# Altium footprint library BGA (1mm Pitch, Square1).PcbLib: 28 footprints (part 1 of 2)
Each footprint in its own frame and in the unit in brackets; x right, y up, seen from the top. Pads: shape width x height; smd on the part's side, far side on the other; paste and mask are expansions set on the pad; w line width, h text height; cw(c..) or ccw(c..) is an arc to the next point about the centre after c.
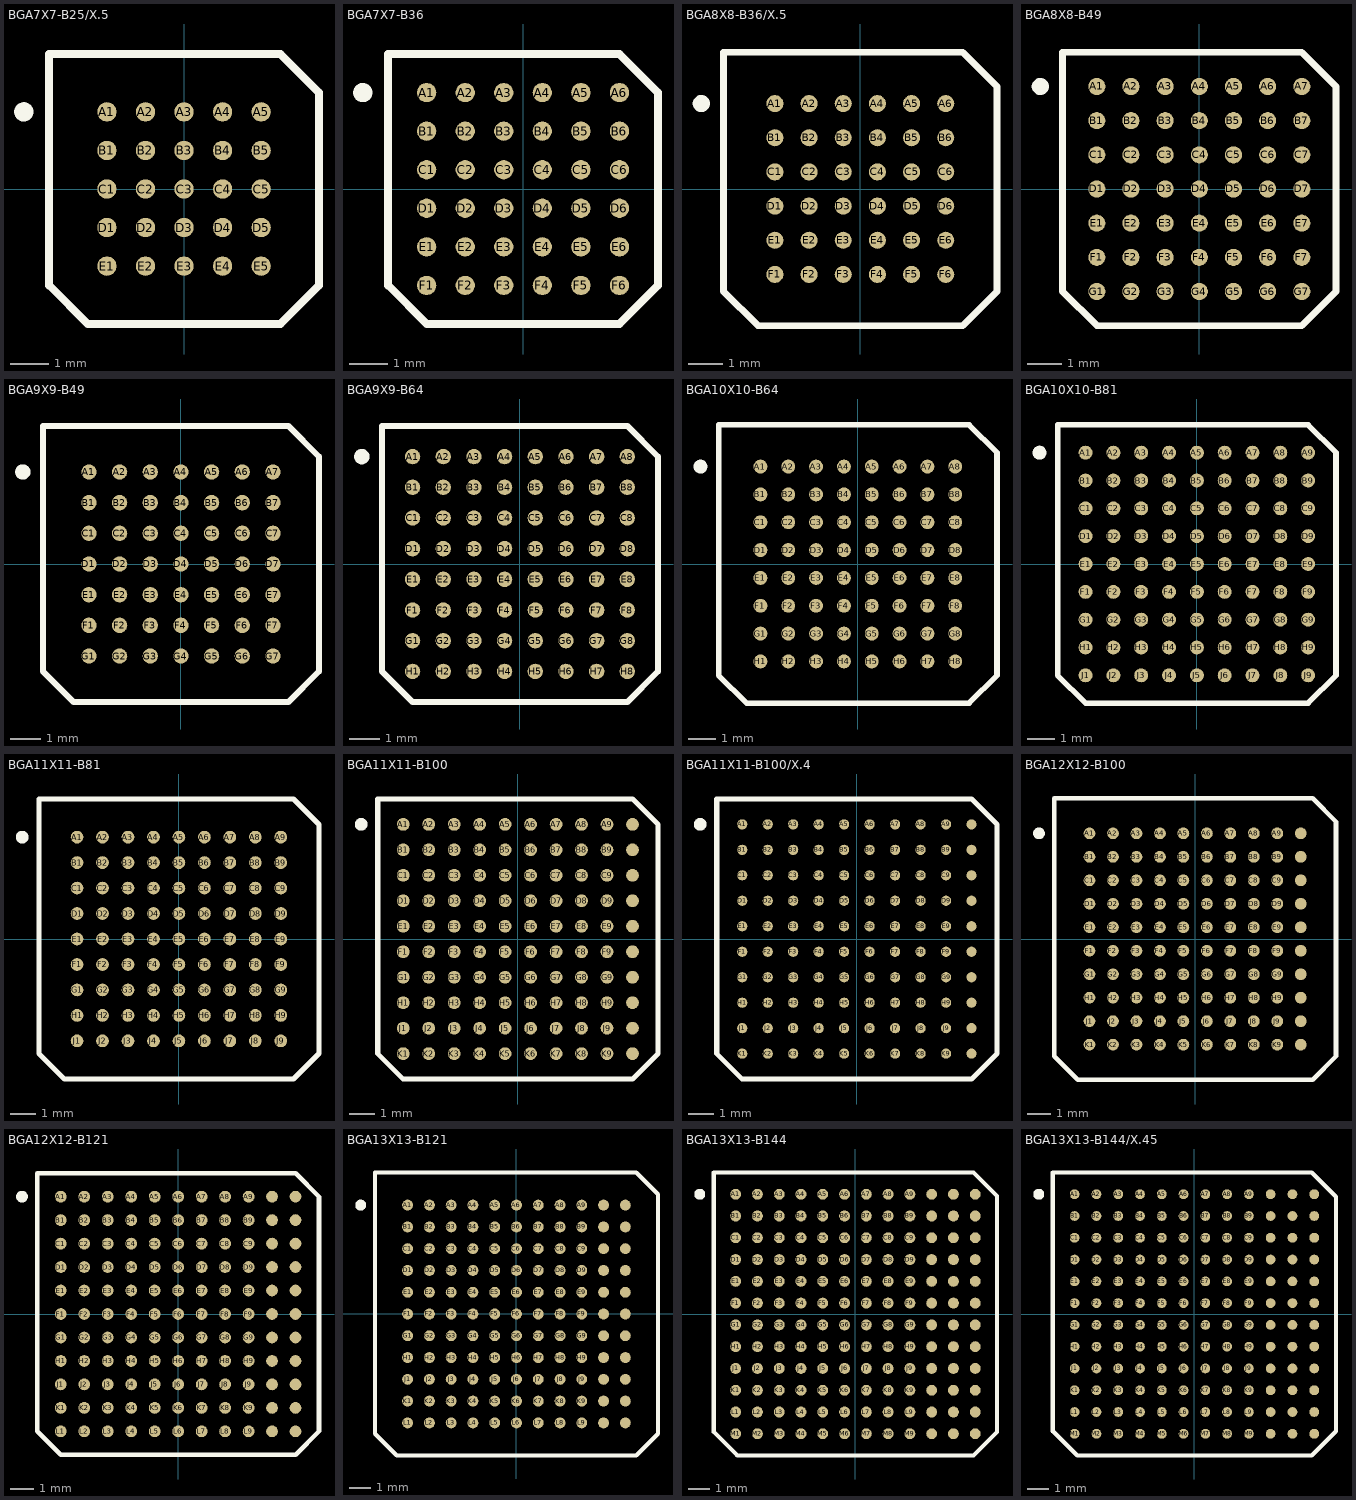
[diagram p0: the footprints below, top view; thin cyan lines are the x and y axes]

## BGA7X7-B25/X.5 [mm]
pads (25):
  round 0.5 smd: A1(-2,2) A2(-1,2) A3(0,2) A4(1,2) A5(2,2) B1(-2,1) B2(-1,1) B3(0,1) B4(1,1) B5(2,1) C1(-2,0) C2(-1,0) C3(0,0) C4(1,0) C5(2,0) D1(-2,-1) D2(-1,-1) D3(0,-1) D4(1,-1) D5(2,-1) E1(-2,-2) E2(-1,-2) E3(0,-2) E4(1,-2) E5(2,-2)
Top Overlay:
  circle w0.25: c-4.155,2 r0.125
  lines w0.2: -3.5,-2.5 -3.5,3.5 2.5,3.5 3.5,2.5 3.5,-2.5 2.5,-3.5 -2.5,-3.5 -3.5,-2.5

## BGA7X7-B36 [mm]
pads (36):
  round 0.5 smd: A1(-2.5,2.5) A2(-1.5,2.5) A3(-0.5,2.5) A4(0.5,2.5) A5(1.5,2.5) A6(2.5,2.5) B1(-2.5,1.5) B2(-1.5,1.5) B3(-0.5,1.5) B4(0.5,1.5) B5(1.5,1.5) B6(2.5,1.5) C1(-2.5,0.5) C2(-1.5,0.5) C3(-0.5,0.5) C4(0.5,0.5) C5(1.5,0.5) C6(2.5,0.5) D1(-2.5,-0.5) D2(-1.5,-0.5) D3(-0.5,-0.5) D4(0.5,-0.5) D5(1.5,-0.5) D6(2.5,-0.5) E1(-2.5,-1.5) E2(-1.5,-1.5) E3(-0.5,-1.5) E4(0.5,-1.5) E5(1.5,-1.5) E6(2.5,-1.5) F1(-2.5,-2.5) F2(-1.5,-2.5) F3(-0.5,-2.5) F4(0.5,-2.5) F5(1.5,-2.5) F6(2.5,-2.5)
Top Overlay:
  circle w0.25: c-4.155,2.5 r0.125
  lines w0.2: -3.5,-2.5 -2.5,-3.5 2.5,-3.5 3.5,-2.5 3.5,2.5 2.5,3.5 -3.5,3.5 -3.5,-2.5

## BGA8X8-B36/X.5 [mm]
pads (36):
  round 0.5 smd: A1(-2.5,2.5) A2(-1.5,2.5) A3(-0.5,2.5) A4(0.5,2.5) A5(1.5,2.5) A6(2.5,2.5) B1(-2.5,1.5) B2(-1.5,1.5) B3(-0.5,1.5) B4(0.5,1.5) B5(1.5,1.5) B6(2.5,1.5) C1(-2.5,0.5) C2(-1.5,0.5) C3(-0.5,0.5) C4(0.5,0.5) C5(1.5,0.5) C6(2.5,0.5) D1(-2.5,-0.5) D2(-1.5,-0.5) D3(-0.5,-0.5) D4(0.5,-0.5) D5(1.5,-0.5) D6(2.5,-0.5) E1(-2.5,-1.5) E2(-1.5,-1.5) E3(-0.5,-1.5) E4(0.5,-1.5) E5(1.5,-1.5) E6(2.5,-1.5) F1(-2.5,-2.5) F2(-1.5,-2.5) F3(-0.5,-2.5) F4(0.5,-2.5) F5(1.5,-2.5) F6(2.5,-2.5)
Top Overlay:
  circle w0.25: c-4.655,2.5 r0.125
  lines w0.2: -4,-3 -3,-4 3,-4 4,-3 4,3 3,4 -4,4 -4,-3

## BGA8X8-B49 [mm]
pads (49):
  round 0.5 smd: A1(-3,3) A2(-2,3) A3(-1,3) A4(0,3) A5(1,3) A6(2,3) A7(3,3) B1(-3,2) B2(-2,2) B3(-1,2) B4(0,2) B5(1,2) B6(2,2) B7(3,2) C1(-3,1) C2(-2,1) C3(-1,1) C4(0,1) C5(1,1) C6(2,1) C7(3,1) D1(-3,0) D2(-2,0) D3(-1,0) D4(0,0) D5(1,0) D6(2,0) D7(3,0) E1(-3,-1) E2(-2,-1) E3(-1,-1) E4(0,-1) E5(1,-1) E6(2,-1) E7(3,-1) F1(-3,-2) F2(-2,-2) F3(-1,-2) F4(0,-2) F5(1,-2) F6(2,-2) F7(3,-2) G1(-3,-3) G2(-2,-3) G3(-1,-3) G4(0,-3) G5(1,-3) G6(2,-3) G7(3,-3)
Top Overlay:
  circle w0.25: c-4.655,3 r0.125
  lines w0.2: -4,-3 -3,-4 3,-4 4,-3 4,3 3,4 -4,4 -4,-3

## BGA9X9-B49 [mm]
pads (49):
  round 0.5 smd: A1(-3,3) A2(-2,3) A3(-1,3) A4(0,3) A5(1,3) A6(2,3) A7(3,3) B1(-3,2) B2(-2,2) B3(-1,2) B4(0,2) B5(1,2) B6(2,2) B7(3,2) C1(-3,1) C2(-2,1) C3(-1,1) C4(0,1) C5(1,1) C6(2,1) C7(3,1) D1(-3,0) D2(-2,0) D3(-1,0) D4(0,0) D5(1,0) D6(2,0) D7(3,0) E1(-3,-1) E2(-2,-1) E3(-1,-1) E4(0,-1) E5(1,-1) E6(2,-1) E7(3,-1) F1(-3,-2) F2(-2,-2) F3(-1,-2) F4(0,-2) F5(1,-2) F6(2,-2) F7(3,-2) G1(-3,-3) G2(-2,-3) G3(-1,-3) G4(0,-3) G5(1,-3) G6(2,-3) G7(3,-3)
Top Overlay:
  circle w0.25: c-5.155,3 r0.125
  lines w0.2: -4.5,-3.5 -3.5,-4.5 3.5,-4.5 4.5,-3.5 4.5,3.5 3.5,4.5 -4.5,4.5 -4.5,-3.5

## BGA9X9-B64 [mm]
pads (64):
  round 0.5 smd: A1(-3.5,3.5) A2(-2.5,3.5) A3(-1.5,3.5) A4(-0.5,3.5) A5(0.5,3.5) A6(1.5,3.5) A7(2.5,3.5) A8(3.5,3.5) B1(-3.5,2.5) B2(-2.5,2.5) B3(-1.5,2.5) B4(-0.5,2.5) B5(0.5,2.5) B6(1.5,2.5) B7(2.5,2.5) B8(3.5,2.5) C1(-3.5,1.5) C2(-2.5,1.5) C3(-1.5,1.5) C4(-0.5,1.5) C5(0.5,1.5) C6(1.5,1.5) C7(2.5,1.5) C8(3.5,1.5) D1(-3.5,0.5) D2(-2.5,0.5) D3(-1.5,0.5) D4(-0.5,0.5) D5(0.5,0.5) D6(1.5,0.5) D7(2.5,0.5) D8(3.5,0.5) E1(-3.5,-0.5) E2(-2.5,-0.5) E3(-1.5,-0.5) E4(-0.5,-0.5) E5(0.5,-0.5) E6(1.5,-0.5) E7(2.5,-0.5) E8(3.5,-0.5) F1(-3.5,-1.5) F2(-2.5,-1.5) F3(-1.5,-1.5) F4(-0.5,-1.5) F5(0.5,-1.5) F6(1.5,-1.5) F7(2.5,-1.5) F8(3.5,-1.5) G1(-3.5,-2.5) G2(-2.5,-2.5) G3(-1.5,-2.5) G4(-0.5,-2.5) G5(0.5,-2.5) G6(1.5,-2.5) G7(2.5,-2.5) G8(3.5,-2.5) H1(-3.5,-3.5) H2(-2.5,-3.5) H3(-1.5,-3.5) H4(-0.5,-3.5) H5(0.5,-3.5) H6(1.5,-3.5) H7(2.5,-3.5) H8(3.5,-3.5)
Top Overlay:
  circle w0.25: c-5.155,3.5 r0.125
  lines w0.2: -4.5,-3.5 -4.5,4.5 3.5,4.5 4.5,3.5 4.5,-3.5 3.5,-4.5 -3.5,-4.5 -4.5,-3.5

## BGA10X10-B64 [mm]
pads (64):
  round 0.5 smd: A1(-3.5,3.5) A2(-2.5,3.5) A3(-1.5,3.5) A4(-0.5,3.5) A5(0.5,3.5) A6(1.5,3.5) A7(2.5,3.5) A8(3.5,3.5) B1(-3.5,2.5) B2(-2.5,2.5) B3(-1.5,2.5) B4(-0.5,2.5) B5(0.5,2.5) B6(1.5,2.5) B7(2.5,2.5) B8(3.5,2.5) C1(-3.5,1.5) C2(-2.5,1.5) C3(-1.5,1.5) C4(-0.5,1.5) C5(0.5,1.5) C6(1.5,1.5) C7(2.5,1.5) C8(3.5,1.5) D1(-3.5,0.5) D2(-2.5,0.5) D3(-1.5,0.5) D4(-0.5,0.5) D5(0.5,0.5) D6(1.5,0.5) D7(2.5,0.5) D8(3.5,0.5) E1(-3.5,-0.5) E2(-2.5,-0.5) E3(-1.5,-0.5) E4(-0.5,-0.5) E5(0.5,-0.5) E6(1.5,-0.5) E7(2.5,-0.5) E8(3.5,-0.5) F1(-3.5,-1.5) F2(-2.5,-1.5) F3(-1.5,-1.5) F4(-0.5,-1.5) F5(0.5,-1.5) F6(1.5,-1.5) F7(2.5,-1.5) F8(3.5,-1.5) G1(-3.5,-2.5) G2(-2.5,-2.5) G3(-1.5,-2.5) G4(-0.5,-2.5) G5(0.5,-2.5) G6(1.5,-2.5) G7(2.5,-2.5) G8(3.5,-2.5) H1(-3.5,-3.5) H2(-2.5,-3.5) H3(-1.5,-3.5) H4(-0.5,-3.5) H5(0.5,-3.5) H6(1.5,-3.5) H7(2.5,-3.5) H8(3.5,-3.5)
Top Overlay:
  circle w0.25: c-5.655,3.5 r0.125
  lines w0.2: -5,-4 -4,-5 4,-5 5,-4 5,4 4,5 -5,5 -5,-4

## BGA10X10-B81 [mm]
pads (81):
  round 0.5 smd: A1(-4,4) A2(-3,4) A3(-2,4) A4(-1,4) A5(0,4) A6(1,4) A7(2,4) A8(3,4) A9(4,4) B1(-4,3) B2(-3,3) B3(-2,3) B4(-1,3) B5(0,3) B6(1,3) B7(2,3) B8(3,3) B9(4,3) C1(-4,2) C2(-3,2) C3(-2,2) C4(-1,2) C5(0,2) C6(1,2) C7(2,2) C8(3,2) C9(4,2) D1(-4,1) D2(-3,1) D3(-2,1) D4(-1,1) D5(0,1) D6(1,1) D7(2,1) D8(3,1) D9(4,1) E1(-4,0) E2(-3,0) E3(-2,0) E4(-1,0) E5(0,0) E6(1,0) E7(2,0) E8(3,0) E9(4,0) F1(-4,-1) F2(-3,-1) F3(-2,-1) F4(-1,-1) F5(0,-1) F6(1,-1) F7(2,-1) F8(3,-1) F9(4,-1) G1(-4,-2) G2(-3,-2) G3(-2,-2) G4(-1,-2) G5(0,-2) G6(1,-2) G7(2,-2) G8(3,-2) G9(4,-2) H1(-4,-3) H2(-3,-3) H3(-2,-3) H4(-1,-3) H5(0,-3) H6(1,-3) H7(2,-3) H8(3,-3) H9(4,-3) J1(-4,-4) J2(-3,-4) J3(-2,-4) J4(-1,-4) J5(0,-4) J6(1,-4) J7(2,-4) J8(3,-4) J9(4,-4)
Top Overlay:
  circle w0.25: c-5.655,4 r0.125
  lines w0.2: -5,-4 -4,-5 4,-5 5,-4 5,4 4,5 -5,5 -5,-4

## BGA11X11-B81 [mm]
pads (81):
  round 0.5 smd: A1(-4,4) A2(-3,4) A3(-2,4) A4(-1,4) A5(0,4) A6(1,4) A7(2,4) A8(3,4) A9(4,4) B1(-4,3) B2(-3,3) B3(-2,3) B4(-1,3) B5(0,3) B6(1,3) B7(2,3) B8(3,3) B9(4,3) C1(-4,2) C2(-3,2) C3(-2,2) C4(-1,2) C5(0,2) C6(1,2) C7(2,2) C8(3,2) C9(4,2) D1(-4,1) D2(-3,1) D3(-2,1) D4(-1,1) D5(0,1) D6(1,1) D7(2,1) D8(3,1) D9(4,1) E1(-4,0) E2(-3,0) E3(-2,0) E4(-1,0) E5(0,0) E6(1,0) E7(2,0) E8(3,0) E9(4,0) F1(-4,-1) F2(-3,-1) F3(-2,-1) F4(-1,-1) F5(0,-1) F6(1,-1) F7(2,-1) F8(3,-1) F9(4,-1) G1(-4,-2) G2(-3,-2) G3(-2,-2) G4(-1,-2) G5(0,-2) G6(1,-2) G7(2,-2) G8(3,-2) G9(4,-2) H1(-4,-3) H2(-3,-3) H3(-2,-3) H4(-1,-3) H5(0,-3) H6(1,-3) H7(2,-3) H8(3,-3) H9(4,-3) J1(-4,-4) J2(-3,-4) J3(-2,-4) J4(-1,-4) J5(0,-4) J6(1,-4) J7(2,-4) J8(3,-4) J9(4,-4)
Top Overlay:
  circle w0.25: c-6.155,4 r0.125
  lines w0.2: -5.5,-4.5 -5.5,5.5 4.5,5.5 5.5,4.5 5.5,-4.5 4.5,-5.5 -4.5,-5.5 -5.5,-4.5

## BGA11X11-B100 [mm]
pads (100):
  round 0.5 smd: A1(-4.5,4.5) A2(-3.5,4.5) A3(-2.5,4.5) A4(-1.5,4.5) A5(-0.5,4.5) A6(0.5,4.5) A7(1.5,4.5) A8(2.5,4.5) A9(3.5,4.5) A10(4.5,4.5) B1(-4.5,3.5) B2(-3.5,3.5) B3(-2.5,3.5) B4(-1.5,3.5) B5(-0.5,3.5) B6(0.5,3.5) B7(1.5,3.5) B8(2.5,3.5) B9(3.5,3.5) B10(4.5,3.5) C1(-4.5,2.5) C2(-3.5,2.5) C3(-2.5,2.5) C4(-1.5,2.5) C5(-0.5,2.5) C6(0.5,2.5) C7(1.5,2.5) C8(2.5,2.5) C9(3.5,2.5) C10(4.5,2.5) D1(-4.5,1.5) D2(-3.5,1.5) D3(-2.5,1.5) D4(-1.5,1.5) D5(-0.5,1.5) D6(0.5,1.5) D7(1.5,1.5) D8(2.5,1.5) D9(3.5,1.5) D10(4.5,1.5) E1(-4.5,0.5) E2(-3.5,0.5) E3(-2.5,0.5) E4(-1.5,0.5) E5(-0.5,0.5) E6(0.5,0.5) E7(1.5,0.5) E8(2.5,0.5) E9(3.5,0.5) E10(4.5,0.5) F1(-4.5,-0.5) F2(-3.5,-0.5) F3(-2.5,-0.5) F4(-1.5,-0.5) F5(-0.5,-0.5) F6(0.5,-0.5) F7(1.5,-0.5) F8(2.5,-0.5) F9(3.5,-0.5) F10(4.5,-0.5) G1(-4.5,-1.5) G2(-3.5,-1.5) G3(-2.5,-1.5) G4(-1.5,-1.5) G5(-0.5,-1.5) G6(0.5,-1.5) G7(1.5,-1.5) G8(2.5,-1.5) G9(3.5,-1.5) G10(4.5,-1.5) H1(-4.5,-2.5) H2(-3.5,-2.5) H3(-2.5,-2.5) H4(-1.5,-2.5) H5(-0.5,-2.5) H6(0.5,-2.5) H7(1.5,-2.5) H8(2.5,-2.5) H9(3.5,-2.5) H10(4.5,-2.5) J1(-4.5,-3.5) J2(-3.5,-3.5) J3(-2.5,-3.5) J4(-1.5,-3.5) J5(-0.5,-3.5) J6(0.5,-3.5) J7(1.5,-3.5) J8(2.5,-3.5) J9(3.5,-3.5) J10(4.5,-3.5) K1(-4.5,-4.5) K2(-3.5,-4.5) K3(-2.5,-4.5) K4(-1.5,-4.5) K5(-0.5,-4.5) K6(0.5,-4.5) K7(1.5,-4.5) K8(2.5,-4.5) K9(3.5,-4.5) K10(4.5,-4.5)
Top Overlay:
  circle w0.25: c-6.15,4.5 r0.125
  lines w0.2: -5.5,-4.5 -5.5,5.5 4.5,5.5 5.5,4.5 5.5,-4.5 4.5,-5.5 -4.5,-5.5 -5.5,-4.5

## BGA11X11-B100/X.4 [mm]
pads (100):
  round 0.4 smd: A1(-4.5,4.5) A2(-3.5,4.5) A3(-2.5,4.5) A4(-1.5,4.5) A5(-0.5,4.5) A6(0.5,4.5) A7(1.5,4.5) A8(2.5,4.5) A9(3.5,4.5) A10(4.5,4.5) B1(-4.5,3.5) B2(-3.5,3.5) B3(-2.5,3.5) B4(-1.5,3.5) B5(-0.5,3.5) B6(0.5,3.5) B7(1.5,3.5) B8(2.5,3.5) B9(3.5,3.5) B10(4.5,3.5) C1(-4.5,2.5) C2(-3.5,2.5) C3(-2.5,2.5) C4(-1.5,2.5) C5(-0.5,2.5) C6(0.5,2.5) C7(1.5,2.5) C8(2.5,2.5) C9(3.5,2.5) C10(4.5,2.5) D1(-4.5,1.5) D2(-3.5,1.5) D3(-2.5,1.5) D4(-1.5,1.5) D5(-0.5,1.5) D6(0.5,1.5) D7(1.5,1.5) D8(2.5,1.5) D9(3.5,1.5) D10(4.5,1.5) E1(-4.5,0.5) E2(-3.5,0.5) E3(-2.5,0.5) E4(-1.5,0.5) E5(-0.5,0.5) E6(0.5,0.5) E7(1.5,0.5) E8(2.5,0.5) E9(3.5,0.5) E10(4.5,0.5) F1(-4.5,-0.5) F2(-3.5,-0.5) F3(-2.5,-0.5) F4(-1.5,-0.5) F5(-0.5,-0.5) F6(0.5,-0.5) F7(1.5,-0.5) F8(2.5,-0.5) F9(3.5,-0.5) F10(4.5,-0.5) G1(-4.5,-1.5) G2(-3.5,-1.5) G3(-2.5,-1.5) G4(-1.5,-1.5) G5(-0.5,-1.5) G6(0.5,-1.5) G7(1.5,-1.5) G8(2.5,-1.5) G9(3.5,-1.5) G10(4.5,-1.5) H1(-4.5,-2.5) H2(-3.5,-2.5) H3(-2.5,-2.5) H4(-1.5,-2.5) H5(-0.5,-2.5) H6(0.5,-2.5) H7(1.5,-2.5) H8(2.5,-2.5) H9(3.5,-2.5) H10(4.5,-2.5) J1(-4.5,-3.5) J2(-3.5,-3.5) J3(-2.5,-3.5) J4(-1.5,-3.5) J5(-0.5,-3.5) J6(0.5,-3.5) J7(1.5,-3.5) J8(2.5,-3.5) J9(3.5,-3.5) J10(4.5,-3.5) K1(-4.5,-4.5) K2(-3.5,-4.5) K3(-2.5,-4.5) K4(-1.5,-4.5) K5(-0.5,-4.5) K6(0.5,-4.5) K7(1.5,-4.5) K8(2.5,-4.5) K9(3.5,-4.5) K10(4.5,-4.5)
Top Overlay:
  circle w0.25: c-6.15,4.5 r0.125
  lines w0.2: -5.5,-4.5 -5.5,5.5 4.5,5.5 5.5,4.5 5.5,-4.5 4.5,-5.5 -4.5,-5.5 -5.5,-4.5

## BGA12X12-B100 [mm]
pads (100):
  round 0.5 smd: A1(-4.5,4.5) A2(-3.5,4.5) A3(-2.5,4.5) A4(-1.5,4.5) A5(-0.5,4.5) A6(0.5,4.5) A7(1.5,4.5) A8(2.5,4.5) A9(3.5,4.5) A10(4.5,4.5) B1(-4.5,3.5) B2(-3.5,3.5) B3(-2.5,3.5) B4(-1.5,3.5) B5(-0.5,3.5) B6(0.5,3.5) B7(1.5,3.5) B8(2.5,3.5) B9(3.5,3.5) B10(4.5,3.5) C1(-4.5,2.5) C2(-3.5,2.5) C3(-2.5,2.5) C4(-1.5,2.5) C5(-0.5,2.5) C6(0.5,2.5) C7(1.5,2.5) C8(2.5,2.5) C9(3.5,2.5) C10(4.5,2.5) D1(-4.5,1.5) D2(-3.5,1.5) D3(-2.5,1.5) D4(-1.5,1.5) D5(-0.5,1.5) D6(0.5,1.5) D7(1.5,1.5) D8(2.5,1.5) D9(3.5,1.5) D10(4.5,1.5) E1(-4.5,0.5) E2(-3.5,0.5) E3(-2.5,0.5) E4(-1.5,0.5) E5(-0.5,0.5) E6(0.5,0.5) E7(1.5,0.5) E8(2.5,0.5) E9(3.5,0.5) E10(4.5,0.5) F1(-4.5,-0.5) F2(-3.5,-0.5) F3(-2.5,-0.5) F4(-1.5,-0.5) F5(-0.5,-0.5) F6(0.5,-0.5) F7(1.5,-0.5) F8(2.5,-0.5) F9(3.5,-0.5) F10(4.5,-0.5) G1(-4.5,-1.5) G2(-3.5,-1.5) G3(-2.5,-1.5) G4(-1.5,-1.5) G5(-0.5,-1.5) G6(0.5,-1.5) G7(1.5,-1.5) G8(2.5,-1.5) G9(3.5,-1.5) G10(4.5,-1.5) H1(-4.5,-2.5) H2(-3.5,-2.5) H3(-2.5,-2.5) H4(-1.5,-2.5) H5(-0.5,-2.5) H6(0.5,-2.5) H7(1.5,-2.5) H8(2.5,-2.5) H9(3.5,-2.5) H10(4.5,-2.5) J1(-4.5,-3.5) J2(-3.5,-3.5) J3(-2.5,-3.5) J4(-1.5,-3.5) J5(-0.5,-3.5) J6(0.5,-3.5) J7(1.5,-3.5) J8(2.5,-3.5) J9(3.5,-3.5) J10(4.5,-3.5) K1(-4.5,-4.5) K2(-3.5,-4.5) K3(-2.5,-4.5) K4(-1.5,-4.5) K5(-0.5,-4.5) K6(0.5,-4.5) K7(1.5,-4.5) K8(2.5,-4.5) K9(3.5,-4.5) K10(4.5,-4.5)
Top Overlay:
  circle w0.25: c-6.655,4.5 r0.125
  lines w0.2: -6,-5 -5,-6 5,-6 6,-5 6,5 5,6 -6,6 -6,-5

## BGA12X12-B121 [mm]
pads (121):
  round 0.5 smd: A1(-5,5) A2(-4,5) A3(-3,5) A4(-2,5) A5(-1,5) A6(0,5) A7(1,5) A8(2,5) A9(3,5) A10(4,5) A11(5,5) B1(-5,4) B2(-4,4) B3(-3,4) B4(-2,4) B5(-1,4) B6(0,4) B7(1,4) B8(2,4) B9(3,4) B10(4,4) B11(5,4) C1(-5,3) C2(-4,3) C3(-3,3) C4(-2,3) C5(-1,3) C6(0,3) C7(1,3) C8(2,3) C9(3,3) C10(4,3) C11(5,3) D1(-5,2) D2(-4,2) D3(-3,2) D4(-2,2) D5(-1,2) D6(0,2) D7(1,2) D8(2,2) D9(3,2) D10(4,2) D11(5,2) E1(-5,1) E2(-4,1) E3(-3,1) E4(-2,1) E5(-1,1) E6(0,1) E7(1,1) E8(2,1) E9(3,1) E10(4,1) E11(5,1) F1(-5,0) F2(-4,0) F3(-3,0) F4(-2,0) F5(-1,0) F6(0,0) F7(1,0) F8(2,0) F9(3,0) F10(4,0) F11(5,0) G1(-5,-1) G2(-4,-1) G3(-3,-1) G4(-2,-1) G5(-1,-1) G6(0,-1) G7(1,-1) G8(2,-1) G9(3,-1) G10(4,-1) G11(5,-1) H1(-5,-2) H2(-4,-2) H3(-3,-2) H4(-2,-2) H5(-1,-2) H6(0,-2) H7(1,-2) H8(2,-2) H9(3,-2) H10(4,-2) H11(5,-2) J1(-5,-3) J2(-4,-3) J3(-3,-3) J4(-2,-3) J5(-1,-3) J6(0,-3) J7(1,-3) J8(2,-3) J9(3,-3) J10(4,-3) J11(5,-3) K1(-5,-4) K2(-4,-4) K3(-3,-4) K4(-2,-4) K5(-1,-4) K6(0,-4) K7(1,-4) K8(2,-4) K9(3,-4) K10(4,-4) K11(5,-4) L1(-5,-5) L2(-4,-5) L3(-3,-5) L4(-2,-5) L5(-1,-5) L6(0,-5) L7(1,-5) L8(2,-5) L9(3,-5) L10(4,-5) L11(5,-5)
Top Overlay:
  circle w0.25: c-6.655,5 r0.125
  lines w0.2: -6,-5 -5,-6 5,-6 6,-5 6,5 5,6 -6,6 -6,-5

## BGA13X13-B121 [mm]
pads (121):
  round 0.5 smd: A1(-5,5) A2(-4,5) A3(-3,5) A4(-2,5) A5(-1,5) A6(0,5) A7(1,5) A8(2,5) A9(3,5) A10(4,5) A11(5,5) B1(-5,4) B2(-4,4) B3(-3,4) B4(-2,4) B5(-1,4) B6(0,4) B7(1,4) B8(2,4) B9(3,4) B10(4,4) B11(5,4) C1(-5,3) C2(-4,3) C3(-3,3) C4(-2,3) C5(-1,3) C6(0,3) C7(1,3) C8(2,3) C9(3,3) C10(4,3) C11(5,3) D1(-5,2) D2(-4,2) D3(-3,2) D4(-2,2) D5(-1,2) D6(0,2) D7(1,2) D8(2,2) D9(3,2) D10(4,2) D11(5,2) E1(-5,1) E2(-4,1) E3(-3,1) E4(-2,1) E5(-1,1) E6(0,1) E7(1,1) E8(2,1) E9(3,1) E10(4,1) E11(5,1) F1(-5,0) F2(-4,0) F3(-3,0) F4(-2,0) F5(-1,0) F6(0,0) F7(1,0) F8(2,0) F9(3,0) F10(4,0) F11(5,0) G1(-5,-1) G2(-4,-1) G3(-3,-1) G4(-2,-1) G5(-1,-1) G6(0,-1) G7(1,-1) G8(2,-1) G9(3,-1) G10(4,-1) G11(5,-1) H1(-5,-2) H2(-4,-2) H3(-3,-2) H4(-2,-2) H5(-1,-2) H6(0,-2) H7(1,-2) H8(2,-2) H9(3,-2) H10(4,-2) H11(5,-2) J1(-5,-3) J2(-4,-3) J3(-3,-3) J4(-2,-3) J5(-1,-3) J6(0,-3) J7(1,-3) J8(2,-3) J9(3,-3) J10(4,-3) J11(5,-3) K1(-5,-4) K2(-4,-4) K3(-3,-4) K4(-2,-4) K5(-1,-4) K6(0,-4) K7(1,-4) K8(2,-4) K9(3,-4) K10(4,-4) K11(5,-4) L1(-5,-5) L2(-4,-5) L3(-3,-5) L4(-2,-5) L5(-1,-5) L6(0,-5) L7(1,-5) L8(2,-5) L9(3,-5) L10(4,-5) L11(5,-5)
Top Overlay:
  circle w0.25: c-7.155,5 r0.125
  lines w0.2: -6.5,-5.5 -5.5,-6.5 5.5,-6.5 6.5,-5.5 6.5,5.5 5.5,6.5 -6.5,6.5 -6.5,-5.5

## BGA13X13-B144 [mm]
pads (144):
  round 0.5 smd: A1(-5.5,5.5) A2(-4.5,5.5) A3(-3.5,5.5) A4(-2.5,5.5) A5(-1.5,5.5) A6(-0.5,5.5) A7(0.5,5.5) A8(1.5,5.5) A9(2.5,5.5) A10(3.5,5.5) A11(4.5,5.5) A12(5.5,5.5) B1(-5.5,4.5) B2(-4.5,4.5) B3(-3.5,4.5) B4(-2.5,4.5) B5(-1.5,4.5) B6(-0.5,4.5) B7(0.5,4.5) B8(1.5,4.5) B9(2.5,4.5) B10(3.5,4.5) B11(4.5,4.5) B12(5.5,4.5) C1(-5.5,3.5) C2(-4.5,3.5) C3(-3.5,3.5) C4(-2.5,3.5) C5(-1.5,3.5) C6(-0.5,3.5) C7(0.5,3.5) C8(1.5,3.5) C9(2.5,3.5) C10(3.5,3.5) C11(4.5,3.5) C12(5.5,3.5) D1(-5.5,2.5) D2(-4.5,2.5) D3(-3.5,2.5) D4(-2.5,2.5) D5(-1.5,2.5) D6(-0.5,2.5) D7(0.5,2.5) D8(1.5,2.5) D9(2.5,2.5) D10(3.5,2.5) D11(4.5,2.5) D12(5.5,2.5) E1(-5.5,1.5) E2(-4.5,1.5) E3(-3.5,1.5) E4(-2.5,1.5) E5(-1.5,1.5) E6(-0.5,1.5) E7(0.5,1.5) E8(1.5,1.5) E9(2.5,1.5) E10(3.5,1.5) E11(4.5,1.5) E12(5.5,1.5) F1(-5.5,0.5) F2(-4.5,0.5) F3(-3.5,0.5) F4(-2.5,0.5) F5(-1.5,0.5) F6(-0.5,0.5) F7(0.5,0.5) F8(1.5,0.5) F9(2.5,0.5) F10(3.5,0.5) F11(4.5,0.5) F12(5.5,0.5) G1(-5.5,-0.5) G2(-4.5,-0.5) G3(-3.5,-0.5) G4(-2.5,-0.5) G5(-1.5,-0.5) G6(-0.5,-0.5) G7(0.5,-0.5) G8(1.5,-0.5) G9(2.5,-0.5) G10(3.5,-0.5) G11(4.5,-0.5) G12(5.5,-0.5) H1(-5.5,-1.5) H2(-4.5,-1.5) H3(-3.5,-1.5) H4(-2.5,-1.5) H5(-1.5,-1.5) H6(-0.5,-1.5) H7(0.5,-1.5) H8(1.5,-1.5) H9(2.5,-1.5) H10(3.5,-1.5) H11(4.5,-1.5) H12(5.5,-1.5) J1(-5.5,-2.5) J2(-4.5,-2.5) J3(-3.5,-2.5) J4(-2.5,-2.5) J5(-1.5,-2.5) J6(-0.5,-2.5) J7(0.5,-2.5) J8(1.5,-2.5) J9(2.5,-2.5) J10(3.5,-2.5) J11(4.5,-2.5) J12(5.5,-2.5) K1(-5.5,-3.5) K2(-4.5,-3.5) K3(-3.5,-3.5) K4(-2.5,-3.5) K5(-1.5,-3.5) K6(-0.5,-3.5) K7(0.5,-3.5) K8(1.5,-3.5) K9(2.5,-3.5) K10(3.5,-3.5) K11(4.5,-3.5) K12(5.5,-3.5) L1(-5.5,-4.5) L2(-4.5,-4.5) L3(-3.5,-4.5) L4(-2.5,-4.5) L5(-1.5,-4.5) L6(-0.5,-4.5) L7(0.5,-4.5) L8(1.5,-4.5) L9(2.5,-4.5) L10(3.5,-4.5) L11(4.5,-4.5) L12(5.5,-4.5) M1(-5.5,-5.5) M2(-4.5,-5.5) M3(-3.5,-5.5) M4(-2.5,-5.5) M5(-1.5,-5.5) M6(-0.5,-5.5) M7(0.5,-5.5) M8(1.5,-5.5) M9(2.5,-5.5) M10(3.5,-5.5) M11(4.5,-5.5) M12(5.5,-5.5)
Top Overlay:
  circle w0.25: c-7.15,5.5 r0.125
  lines w0.2: -6.5,-5.419 -6.5,6.5 5.419,6.5 6.5,5.419 6.5,-5.419 5.419,-6.5 -5.419,-6.5 -6.5,-5.419

## BGA13X13-B144/X.45 [mm]
pads (144):
  round 0.45 smd: A1(-5.5,5.5) A2(-4.5,5.5) A3(-3.5,5.5) A4(-2.5,5.5) A5(-1.5,5.5) A6(-0.5,5.5) A7(0.5,5.5) A8(1.5,5.5) A9(2.5,5.5) A10(3.5,5.5) A11(4.5,5.5) A12(5.5,5.5) B1(-5.5,4.5) B2(-4.5,4.5) B3(-3.5,4.5) B4(-2.5,4.5) B5(-1.5,4.5) B6(-0.5,4.5) B7(0.5,4.5) B8(1.5,4.5) B9(2.5,4.5) B10(3.5,4.5) B11(4.5,4.5) B12(5.5,4.5) C1(-5.5,3.5) C2(-4.5,3.5) C3(-3.5,3.5) C4(-2.5,3.5) C5(-1.5,3.5) C6(-0.5,3.5) C7(0.5,3.5) C8(1.5,3.5) C9(2.5,3.5) C10(3.5,3.5) C11(4.5,3.5) C12(5.5,3.5) D1(-5.5,2.5) D2(-4.5,2.5) D3(-3.5,2.5) D4(-2.5,2.5) D5(-1.5,2.5) D6(-0.5,2.5) D7(0.5,2.5) D8(1.5,2.5) D9(2.5,2.5) D10(3.5,2.5) D11(4.5,2.5) D12(5.5,2.5) E1(-5.5,1.5) E2(-4.5,1.5) E3(-3.5,1.5) E4(-2.5,1.5) E5(-1.5,1.5) E6(-0.5,1.5) E7(0.5,1.5) E8(1.5,1.5) E9(2.5,1.5) E10(3.5,1.5) E11(4.5,1.5) E12(5.5,1.5) F1(-5.5,0.5) F2(-4.5,0.5) F3(-3.5,0.5) F4(-2.5,0.5) F5(-1.5,0.5) F6(-0.5,0.5) F7(0.5,0.5) F8(1.5,0.5) F9(2.5,0.5) F10(3.5,0.5) F11(4.5,0.5) F12(5.5,0.5) G1(-5.5,-0.5) G2(-4.5,-0.5) G3(-3.5,-0.5) G4(-2.5,-0.5) G5(-1.5,-0.5) G6(-0.5,-0.5) G7(0.5,-0.5) G8(1.5,-0.5) G9(2.5,-0.5) G10(3.5,-0.5) G11(4.5,-0.5) G12(5.5,-0.5) H1(-5.5,-1.5) H2(-4.5,-1.5) H3(-3.5,-1.5) H4(-2.5,-1.5) H5(-1.5,-1.5) H6(-0.5,-1.5) H7(0.5,-1.5) H8(1.5,-1.5) H9(2.5,-1.5) H10(3.5,-1.5) H11(4.5,-1.5) H12(5.5,-1.5) J1(-5.5,-2.5) J2(-4.5,-2.5) J3(-3.5,-2.5) J4(-2.5,-2.5) J5(-1.5,-2.5) J6(-0.5,-2.5) J7(0.5,-2.5) J8(1.5,-2.5) J9(2.5,-2.5) J10(3.5,-2.5) J11(4.5,-2.5) J12(5.5,-2.5) K1(-5.5,-3.5) K2(-4.5,-3.5) K3(-3.5,-3.5) K4(-2.5,-3.5) K5(-1.5,-3.5) K6(-0.5,-3.5) K7(0.5,-3.5) K8(1.5,-3.5) K9(2.5,-3.5) K10(3.5,-3.5) K11(4.5,-3.5) K12(5.5,-3.5) L1(-5.5,-4.5) L2(-4.5,-4.5) L3(-3.5,-4.5) L4(-2.5,-4.5) L5(-1.5,-4.5) L6(-0.5,-4.5) L7(0.5,-4.5) L8(1.5,-4.5) L9(2.5,-4.5) L10(3.5,-4.5) L11(4.5,-4.5) L12(5.5,-4.5) M1(-5.5,-5.5) M2(-4.5,-5.5) M3(-3.5,-5.5) M4(-2.5,-5.5) M5(-1.5,-5.5) M6(-0.5,-5.5) M7(0.5,-5.5) M8(1.5,-5.5) M9(2.5,-5.5) M10(3.5,-5.5) M11(4.5,-5.5) M12(5.5,-5.5)
Top Overlay:
  circle w0.25: c-7.15,5.5 r0.125
  lines w0.2: -6.5,-5.384 -5.384,-6.5 5.384,-6.5 6.5,-5.384 6.5,5.384 5.384,6.5 -6.5,6.5 -6.5,-5.384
